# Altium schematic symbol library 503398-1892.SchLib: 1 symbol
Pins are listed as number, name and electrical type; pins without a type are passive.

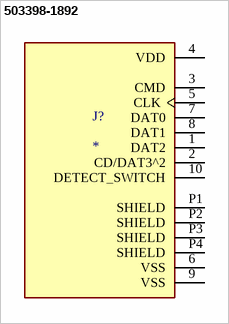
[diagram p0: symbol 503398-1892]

## 503398-1892
designator J?
9 (8 + 1) Position Card Connector Secure Digital - microSDâ„¢ Surface Mount, Right Angle Gold; MP: 5033981892; MF: Molex
footprint MOLEX_503398-1892
pins: 1 DAT2, 2 CD/DAT3^2, 3 CMD, 4 VDD (power), 5 CLK, 6 VSS (power), 7 DAT0, 8 DAT1, 9 VSS (power), 10 DETECT_SWITCH, P1 SHIELD, P2 SHIELD, P3 SHIELD, P4 SHIELD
